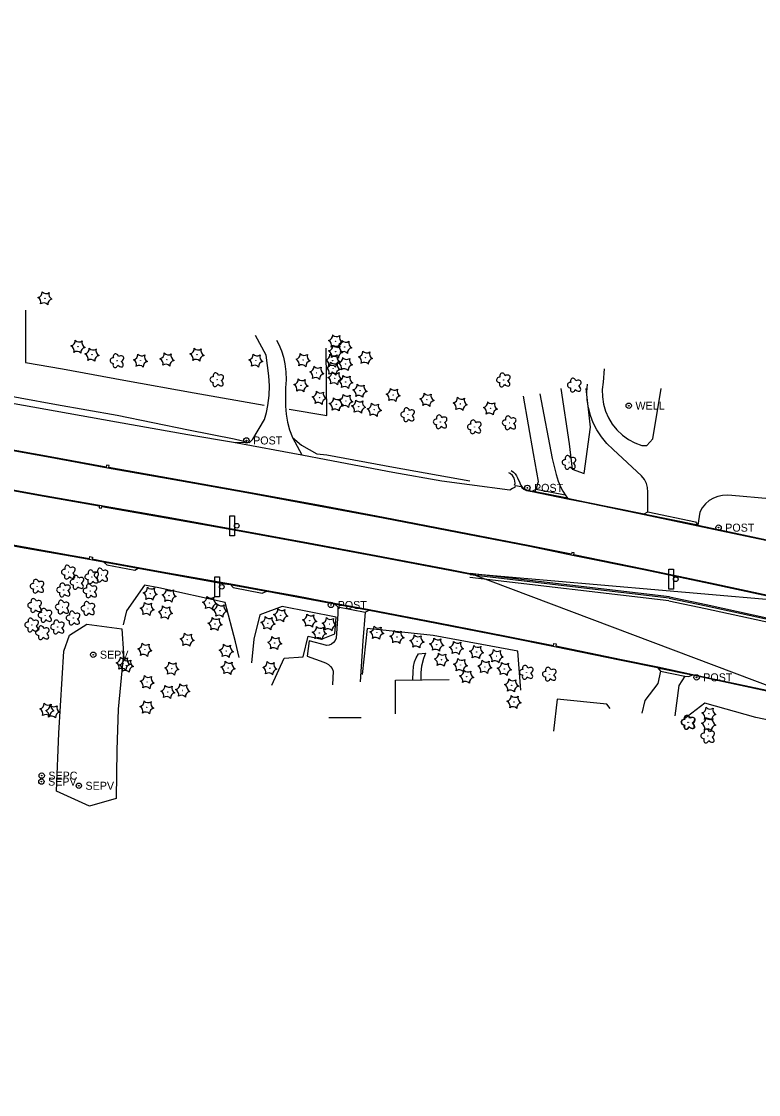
# Model space of a CAD drawing. Extents: x 588843 to 2552415, y 180129 to 269402.
# Drawn here: x 589402 to 589955, y 186560 to 187364 of the extents above; entities that cross this region are included whole.
import ezdxf

# ---------------------------------------------------------------- set-up
doc = ezdxf.new("R2010")
doc.units = 0
for name, color, linetype in [('Default', 7, 'Continuous'), ('E_BLD', 7, 'Continuous'), ('E_FEN_Generic', 7, 'Continuous'), ('E_LAND_TreeLine', 7, 'Continuous'), ('E_LAND_Vegetation', 7, 'Continuous'), ('E_MISCPROP', 7, 'Continuous'), ('E_MISCPROP_Septic', 7, 'Continuous'), ('E_MISCPROP_Well', 7, 'Continuous'), ('E_RDWY', 7, 'Continuous'), ('E_RDWY_AsphConc', 7, 'Continuous'), ('E_RDWY_C_and_G', 7, 'Continuous'), ('E_RDWY_Gravel', 7, 'Continuous'), ('E_SGN', 7, 'Continuous'), ('P_RDWY_C_and_G_30', 7, 'Continuous'), ('P_RDWY_C_and_GFace', 7, 'Continuous'), ('P_RDWY_LaneEdge', 7, 'Continuous')]:
    doc.layers.add(name, color=color, linetype=linetype)

# ---------------------------------------------------------------- blocks, each defined once
blk = doc.blocks.new('CTRE_2')
at = {"layer": 'E_LAND_Vegetation'}
blk.add_circle((0, 0), 0.223, dxfattribs=at)
for centre, start, end in [((-12, 9), 280.2067, 5.9716), ((-13.8, -5.9), 340.2113, 65.9762), ((1.8, 14.9), 220.2113, 305.9762), ((13.8, 5.9), 160.2113, 245.9762), ((-1.8, -14.9), 40.2113, 125.9762), ((12, -9), 100.2511, 185.9272)]:
    blk.add_arc(centre, 7.87, start, end, dxfattribs=at)
blk = doc.blocks.new('DTRE_2')
at = {"layer": 'E_LAND_Vegetation'}
blk.add_circle((-0.2, 0), 0.183, dxfattribs=at)
for centre, major_axis, ratio in [((-5.9, 0.2), (4.93, -0.12), 0.832022), ((-1.9, 5.3), (1.36, -4.98), 0.782863), ((4.1, 2.7), (-5.27, -2.93), 0.691916), ((-2.5, -5.2), (1.8, 4.86), 0.716896), ((3.5, -3.7), (-5.01, 4.58), 0.560249)]:
    blk.add_ellipse(centre, major_axis=major_axis, ratio=ratio, start_param=1.570796, end_param=4.712389, dxfattribs=at)
blk = doc.blocks.new('POST')
at = {"layer": 'E_MISCPROP'}
for radius in [4, 0.5]:
    blk.add_circle((0, 0), radius, dxfattribs=at)
blk.add_text('POST', height=12, dxfattribs=at).set_placement((10, -6))
blk = doc.blocks.new('SEPC')
at = {"layer": 'E_MISCPROP_Septic'}
for radius in [4, 0.5]:
    blk.add_circle((0, 0), radius, dxfattribs=at)
blk.add_text('SEPC', height=12, dxfattribs=at).set_placement((10, -6))
blk = doc.blocks.new('SEPV')
at = {"layer": 'E_MISCPROP_Septic'}
for radius in [4, 0.5]:
    blk.add_circle((0, 0), radius, dxfattribs=at)
blk.add_text('SEPV', height=12, dxfattribs=at).set_placement((10, -6))
blk = doc.blocks.new('SGN')
at = {"layer": 'E_SGN'}
blk.add_lwpolyline([(-3.5, -15), (-10.5, -15), (-10.5, 15), (-3.5, 15)], close=True, dxfattribs=at)
blk.add_circle((0, 0), 3.5, dxfattribs=at)
blk = doc.blocks.new('WELL')
at = {"layer": 'E_MISCPROP_Well'}
for radius in [4, 0.5]:
    blk.add_circle((0, 0), radius, dxfattribs=at)
blk.add_text('WELL', height=12, dxfattribs=at).set_placement((10, -6))

msp = doc.modelspace()

# ---------------------------------------------------------------- linework, layer by layer
at = {"layer": 'Default'}
msp.add_lwpolyline([(591615.09, 187246.23), (591637.48, 187198.53), (591342.5, 186657.05), (591340.04, 186646.33), (591325.15, 186588.94), (591314.68, 186544.52), (590335.16, 185755.94), (590089.6, 186237.3), (590063.71, 186267.8), (589984.27, 186602.34), (590048.74, 186666.43), (590044.21, 186706.17), (589965.01, 186852.44), (589966.96, 186864.3), (589738.46, 186950.56), (589980.48, 186929.54), (589980.82, 186932.54), (589987.79, 186967.01), (589988.43, 186969.95), (590832.85, 187364.29), (591607.16, 187360.88), (591615.35, 187246.35)], dxfattribs=at)
at = {"layer": 'E_BLD'}
for points in [[(589682.51, 186845.31), (589682.41, 186870.77), (589722.57, 186871.09)], [(589843.35, 186849.49), (589840.77, 186852.62), (589803.54, 186856.43), (589800.87, 186832.43)], [(589632.35, 186842.74), (589656.72, 186842.67)]]:
    msp.add_lwpolyline(points, dxfattribs=at)
at = {"layer": 'E_FEN_Generic'}
for points in [[(589405.08, 187147.87), (589405.03, 187108.65), (589432.7, 187103.92), (589478.73, 187095.47), (589531.54, 187085.92), (589583.95, 187076.68)], [(589631.02, 187069.05), (589630.46, 187119.36)], [(589602.77, 187073.62), (589631.02, 187069.05)]]:
    msp.add_lwpolyline(points, dxfattribs=at)
at = {"layer": 'E_LAND_TreeLine'}
for points in [[(589806.4, 187089.18), (589812.59, 187047.85), (589814.83, 187028.66), (589823.77, 187025.6), (589828.69, 187060.14), (589825.39, 187089.23)], [(589565.11, 186887.69), (589562.51, 186899.32), (589554.64, 186928.98), (589504.96, 186939.84), (589494.38, 186941.78), (589480.9, 186922.67), (589478.19, 186912.07)], [(589589.61, 186866.88), (589598.87, 186887.08), (589613.12, 186888.16), (589616.87, 186903.71), (589626.95, 186901.3), (589636.9, 186905.36), (589637.83, 186917.74), (589597.41, 186925.8), (589580.62, 186919.52), (589576.19, 186901.45), (589574.43, 186883.69)], [(589776.39, 186863.13), (589774.02, 186892.48), (589710.6, 186904.03), (589661.22, 186909.42), (589657.46, 186874.81)], [(590014.98, 186732.45), (590063.58, 186738.57), (590112.84, 186742.66), (590160.88, 186749.13), (590170.83, 186760.5), (590178.14, 186789.72), (590132.33, 186804.85), (590080.03, 186813.95), (590043.49, 186822.21), (589999.48, 186833.03), (589952.51, 186842.61), (589914.19, 186853.29), (589898.07, 186840.93)]]:
    msp.add_lwpolyline(points, dxfattribs=at)
at = {"layer": 'E_MISCPROP_Septic'}
msp.add_lwpolyline([(589433.87, 186892.43), (589437.99, 186904.25), (589451.03, 186912.69), (589477.28, 186909.03), (589478.46, 186890.74), (589474.46, 186848.94), (589473.62, 186818.31), (589473.15, 186781.94), (589453.13, 186776.31), (589428.41, 186787.56), (589430.04, 186830.87)], close=True, dxfattribs=at)
at = {"layer": 'E_RDWY'}
for points in [[(589561.02, 187048.9), (589573.02, 187048.74), (589575.56, 187051.35), (589584.2, 187066.08), (589585.61, 187071.3), (589586.7, 187076.6), (589586.7, 187076.6), (589587.62, 187083.94), (589587.9, 187091.33), (589587.54, 187098.72), (589587.54, 187098.72), (589585.46, 187114.21), (589577.41, 187128.97)], [(589593.28, 187125.56), (589595.04, 187122.11), (589596.89, 187117.44), (589598.36, 187112.63), (589599.43, 187107.73), (589599.43, 187107.73), (589600.19, 187101.72), (589600.35, 187095.68), (589599.92, 187089.64), (589599.92, 187089.64), (589599.9, 187075.88), (589600.36, 187069.89), (589601.39, 187063.96), (589602.98, 187058.16), (589602.98, 187058.16), (589605.16, 187052.42), (589605.16, 187052.42), (589612.18, 187039.61)], [(589838.72, 187103.98), (589838.05, 187094.08), (589837.42, 187088.59), (589837.51, 187083.07), (589838.34, 187077.6), (589839.87, 187072.3), (589842.09, 187067.24), (589844.96, 187062.52), (589844.96, 187062.52), (589844.96, 187062.52), (589848.44, 187058.19), (589852.47, 187054.37), (589856.97, 187051.11), (589861.86, 187048.48), (589867.06, 187046.52), (589867.06, 187046.52), (589870.94, 187046.41), (589875.24, 187051.53), (589881.49, 187089.14)], [(589871.7, 186996.71), (589871.68, 187011.63), (589871.42, 187014.92), (589870.54, 187018.09), (589870.54, 187018.09), (589869, 187021.14), (589866.9, 187023.82), (589866.9, 187023.82), (589845.56, 187043.63), (589840.92, 187048.01), (589836.82, 187052.89), (589833.32, 187058.22), (589833.32, 187058.22), (589830.63, 187063.5), (589828.54, 187069.05), (589827.05, 187074.78), (589826.19, 187080.65), (589825.97, 187086.57), (589826.4, 187092.48), (589826.4, 187092.48), (589826.4, 187092.48)], [(589787.9, 187013.85), (589789.53, 187019.46), (589785.99, 187040.49), (589778.28, 187083.47)], [(589790.51, 187085.17), (589799.93, 187036.88), (589802.89, 187024.83), (589804.34, 187019.84), (589806.35, 187015.04), (589806.35, 187015.04), (589807.82, 187012.27), (589809.49, 187009.61), (589809.49, 187009.61)], [(589965.6, 187090.54), (589965.17, 187054), (589962.88, 187006.44), (589934.47, 187009.04), (589931, 187009.36), (589927.53, 187009.14), (589924.13, 187008.39), (589920.89, 187007.11), (589920.89, 187007.11), (589917.66, 187005.2), (589914.81, 187002.77), (589912.39, 186999.9), (589910.49, 186996.67), (589910.49, 186996.67), (589909.16, 186986.87)], [(589372.62, 187082.17), (589427.26, 187072.37), (589473.22, 187064.16), (589526.69, 187054.74), (589561.02, 187048.9), (589612.18, 187039.61), (589630.34, 187036.06), (589680.41, 187026.44), (589717.23, 187020), (589737.9, 187017.33), (589768.13, 187013.41), (589770.12, 187014.57), (589772.19, 187015.27), (589772.46, 187016.44), (589776.62, 187015.67), (589777.18, 187014.99), (589778.57, 187013.82), (589778.57, 187013.82), (589780.62, 187012.84), (589780.62, 187012.84), (589784.85, 187011.92), (589811.4, 187006.57), (589824.26, 187003.96), (589868.73, 186994.69), (589908.97, 186986.39), (589925.47, 186982.93), (589984.99, 186970.24)], [(589977.73, 186930.63), (589918.47, 186943.34), (589868.51, 186953.89), (589816.22, 186964.61), (589816.46, 186966), (589814.61, 186966.4), (589814.24, 186964.98), (589781.92, 186971.46), (589730.12, 186981.57), (589673.33, 186992.61), (589624.74, 187001.68), (589571, 187011.48), (589520.88, 187020.41), (589467.58, 187030), (589467.78, 187031.44), (589465.9, 187031.84), (589465.59, 187030.38), (589420.78, 187038.48), (589366.35, 187048.18)], [(589361.36, 187018.98), (589414.74, 187009.38), (589460.39, 187001.28), (589460.18, 186999.88), (589461.93, 186999.54), (589462.2, 187000.92), (589514.68, 186991.65), (589563.86, 186982.74), (589616.98, 186973.1), (589667.83, 186963.63), (589723.19, 186953.07), (589738.52, 186950.06)], [(589353.39, 186979.53), (589404.18, 186970.46), (589440.06, 186964.03), (589453.05, 186961.82), (589453.3, 186963.27), (589455.17, 186962.91), (589454.92, 186961.51), (589463.6, 186959.94), (589489.65, 186955.16), (589507.48, 186951.83), (589554.46, 186943.52), (589558.88, 186942.72), (589586.08, 186937.82), (589608.52, 186933.73), (589636.67, 186928.48), (589662.7, 186923.58), (589713.4, 186913.84), (589765.71, 186903.54), (589800.74, 186896.64), (589801.13, 186898.12), (589802.88, 186897.85), (589802.68, 186896.37), (589851.85, 186886.15), (589879.01, 186880.52), (589905.38, 186874.97), (589960.82, 186863.13)], [(589639.17, 186925.49), (589639.14, 186920.29), (589637.85, 186902.24), (589637.19, 186900.41), (589636.05, 186898.83), (589634.51, 186897.63), (589634.51, 186897.63), (589632.77, 186896.93), (589630.91, 186896.72), (589630.91, 186896.72), (589617.64, 186900.13), (589616.22, 186888.67), (589628.58, 186884.26), (589630.49, 186883.51), (589632.22, 186882.42), (589633.71, 186881.01), (589633.71, 186881.01), (589634.9, 186879.36), (589635.76, 186877.52), (589635.76, 186877.52), (589635.16, 186867.24)], [(589659.78, 186921.54), (589657.91, 186900.04), (589655.97, 186869.37)], [(589880.98, 186877.5), (589879.11, 186868.07), (589869.22, 186855.51), (589867.2, 186845.86)], [(589899.3, 186873.57), (589894.76, 186866.74), (589891.92, 186843.99)]]:
    msp.add_lwpolyline(points, dxfattribs=at)
at = {"layer": 'E_RDWY_AsphConc'}
for points in [[(589784.99, 187012.34), (589787.9, 187013.85), (589809.49, 187009.61), (589811.38, 187007.1)], [(589868.9, 186995.31), (589871.7, 186996.71), (589907.23, 186989.23), (589909.16, 186986.87)], [(589463.47, 186959.44), (589466.05, 186957.19), (589486.94, 186953.09), (589489.53, 186954.56)], [(589558.81, 186942.23), (589560.81, 186940.11), (589582.49, 186935.87), (589585.95, 186937.31)], [(589636.7, 186927.94), (589639.17, 186925.49), (589659.78, 186921.54), (589662.7, 186923)], [(589695.37, 186871.04), (589695.65, 186877.02), (589695.81, 186880.78), (589696.63, 186884.45), (589696.63, 186884.45), (589697.86, 186887.51), (589699.54, 186890.34), (589699.54, 186890.34), (589704.87, 186890.78), (589703.32, 186886.97), (589701.95, 186881.16), (589701.95, 186881.16), (589701.37, 186876.46), (589701.37, 186876.46), (589701.34, 186870.96)], [(589878.86, 186880.04), (589880.98, 186877.5), (589899.3, 186873.57), (589902.34, 186873.3), (589905.08, 186874.55)]]:
    msp.add_lwpolyline(points, dxfattribs=at)
at = {"layer": 'E_RDWY_C_and_G'}
for points in [[(589977.55, 186930.13), (589918.31, 186942.9), (589868.47, 186953.29), (589815.16, 186964.2), (589781.77, 186970.99), (589730, 186981.13), (589673.25, 186992.17), (589624.58, 187001.14), (589570.94, 187010.92), (589520.62, 187019.99), (589466.47, 187029.65), (589420.83, 187037.9), (589366.16, 187047.65)], [(589769.16, 187027.9), (589770.91, 187026.41), (589772.17, 187025.18), (589773.21, 187023.75), (589773.21, 187023.75), (589773.96, 187022.27), (589773.96, 187022.27), (589775.67, 187018.49), (589776.24, 187017.11), (589777.06, 187015.86), (589777.06, 187015.86), (589778.69, 187014.34), (589780.69, 187013.34), (589780.69, 187013.34), (589784.99, 187012.34), (589785.9, 187012.23), (589810.02, 187007.42), (589811.38, 187007.1), (589824.39, 187004.41), (589868.9, 186995.31), (589869.66, 186995.11), (589907.92, 186987.23), (589909.16, 186986.87), (589925.72, 186983.38), (589985.18, 186970.66)], [(589361.45, 187019.53), (589414.83, 187009.91), (589514.78, 186992.2), (589564.07, 186983.31), (589617.16, 186973.61), (589667.99, 186964.17), (589723.28, 186953.52), (589738.46, 186950.56)], [(589771.7, 187016.68), (589772.13, 187018.1), (589771.97, 187020.15), (589771.33, 187022.09), (589771.33, 187022.09), (589770.09, 187024.02), (589768.37, 187025.55), (589768.37, 187025.55), (589767.46, 187026.14)], [(589353.38, 186979.03), (589404.09, 186969.91), (589439.93, 186963.61), (589453.98, 186961.18), (589463.47, 186959.44), (589464.71, 186959.2), (589488.38, 186954.83), (589489.53, 186954.56), (589507.31, 186951.3), (589554.36, 186942.91), (589558.81, 186942.23), (589559.78, 186942.05), (589584.27, 186937.51), (589585.95, 186937.31), (589608.44, 186933.16), (589636.7, 186927.94), (589637.87, 186927.67), (589661.38, 186923.24), (589662.7, 186923), (589713.22, 186913.32), (589765.61, 186903.02), (589801.55, 186895.91), (589851.67, 186885.69), (589878.86, 186880.04), (589880.03, 186879.72), (589903.63, 186874.82), (589905.08, 186874.55), (589960.75, 186862.61)]]:
    msp.add_lwpolyline(points, dxfattribs=at)
at = {"layer": 'E_RDWY_Gravel'}
for points in [[(589014.46, 187248.67), (589012.5, 187215.74), (589012.78, 187204.67), (589013.84, 187193.64), (589013.84, 187193.64), (589015.34, 187184.4), (589017.4, 187175.26), (589017.4, 187175.26), (589025.04, 187159.45), (589039.39, 187149.24), (589063.58, 187143.87), (589113.01, 187134.42), (589164.63, 187124.63), (589219.01, 187114.58), (589273.12, 187104.99), (589323.17, 187096.7), (589373.47, 187087.16), (589428.23, 187077.23), (589473.87, 187069.16), (589527.37, 187058.14), (589561.37, 187051.4), (589573.02, 187048.74)], [(589605.16, 187052.42), (589611.88, 187046.72), (589623.53, 187040.18), (589631.05, 187039.47), (589680.88, 187030.35), (589738.1, 187019.91)]]:
    msp.add_lwpolyline(points, dxfattribs=at)
at = {"layer": 'P_RDWY_C_and_G_30'}
for points in [[(589887.78, 186933.01), (589738.46, 186950.56)], [(589887.78, 186933.01), (589738.46, 186950.56)], [(589887.78, 186933.01), (589915.39, 186927.24), (589985.72, 186911.99)]]:
    msp.add_lwpolyline(points, dxfattribs=at)
at = {"layer": 'P_RDWY_C_and_GFace'}
for points in [[(589887.62, 186932.02), (589738.34, 186949.57)], [(589887.62, 186932.02), (589738.34, 186949.57)], [(589887.62, 186932.02), (589915.18, 186926.26), (589985.51, 186911.01)]]:
    msp.add_lwpolyline(points, dxfattribs=at)
at = {"layer": 'P_RDWY_LaneEdge'}
for points in [[(589887.3, 186930.04), (589738.11, 186947.58)], [(589887.3, 186930.04), (589738.11, 186947.58)], [(589887.3, 186930.04), (589914.76, 186924.31), (589985.08, 186909.06)]]:
    msp.add_lwpolyline(points, dxfattribs=at)

# ---------------------------------------------------------------- block references
at = {"layer": 'E_LAND_Vegetation', "xscale": 0.5, "yscale": 0.5}
for name, p in [('CTRE_2', (589419.63, 187156.86)), ('CTRE_2', (589444.41, 187120.57)), ('CTRE_2', (589637.42, 187124.56)), ('CTRE_2', (589644.35, 187120.4)), ('CTRE_2', (589454.94, 187114.56)), ('CTRE_2', (589511.11, 187110.94)), ('CTRE_2', (589533.62, 187114.6)), ('CTRE_2', (589637.56, 187116.78)), ('CTRE_2', (589659.97, 187112.36)), ('DTRE_2', (589473.83, 187110.01)), ('CTRE_2', (589491.27, 187110.12)), ('CTRE_2', (589577.73, 187110.14)), ('CTRE_2', (589613.16, 187110.49)), ('CTRE_2', (589635.4, 187110.08)), ('CTRE_2', (589635.71, 187104.17)), ('CTRE_2', (589644.91, 187107.53)), ('DTRE_2', (589548.74, 187095.76)), ('CTRE_2', (589623.42, 187100.98)), ('CTRE_2', (589636.92, 187096.92)), ('DTRE_2', (589763.58, 187095.61)), ('CTRE_2', (589611.55, 187091.59)), ('CTRE_2', (589645.12, 187094.15)), ('CTRE_2', (589655.82, 187087.56)), ('DTRE_2', (589816.69, 187091.71)), ('CTRE_2', (589625.33, 187082.25)), ('CTRE_2', (589645.19, 187079.93)), ('CTRE_2', (589680.64, 187084.4)), ('CTRE_2', (589706.01, 187080.76)), ('CTRE_2', (589638.06, 187077.33)), ('CTRE_2', (589654.75, 187075.68)), ('CTRE_2', (589666.51, 187073.27)), ('CTRE_2', (589730.92, 187077.72)), ('CTRE_2', (589753.61, 187074.32)), ('DTRE_2', (589691.79, 187069.56)), ('DTRE_2', (589716.16, 187064.18)), ('DTRE_2', (589767.9, 187063.47)), ('DTRE_2', (589741.71, 187060.43)), ('DTRE_2', (589812.66, 187033.8)), ('DTRE_2', (589437.49, 186951.57)), ('DTRE_2', (589462, 186949.35)), ('DTRE_2', (589443.91, 186943.95)), ('DTRE_2', (589454.99, 186948.03)), ('DTRE_2', (589413.94, 186941.02)), ('DTRE_2', (589433.83, 186938.23)), ('DTRE_2', (589453.71, 186937.55)), ('CTRE_2', (589498.54, 186935.46)), ('CTRE_2', (589512.71, 186933.96)), ('DTRE_2', (589412.19, 186926.58)), ('DTRE_2', (589432.79, 186925.36)), ('CTRE_2', (589543.11, 186928.56)), ('DTRE_2', (589419.94, 186919.25)), ('DTRE_2', (589440.99, 186917.19)), ('DTRE_2', (589452.08, 186924.36)), ('CTRE_2', (589496.27, 186924.05)), ('CTRE_2', (589509.95, 186921.34)), ('CTRE_2', (589550.85, 186922.79)), ('CTRE_2', (589596.33, 186919.3)), ('DTRE_2', (589409.96, 186911.93)), ('DTRE_2', (589429.28, 186910.46)), ('CTRE_2', (589547.17, 186912.7)), ('CTRE_2', (589586.82, 186913.35)), ('CTRE_2', (589618.07, 186915.28)), ('CTRE_2', (589632.73, 186912.63)), ('DTRE_2', (589417.93, 186906.15)), ('CTRE_2', (589625.37, 186906.02)), ('CTRE_2', (589668.42, 186906.2)), ('CTRE_2', (589683.51, 186903.02)), ('CTRE_2', (589526.29, 186900.94)), ('CTRE_2', (589591.91, 186898.44)), ('CTRE_2', (589698.56, 186899.67)), ('CTRE_2', (589713.27, 186897.3)), ('CTRE_2', (589728.08, 186894.81)), ('CTRE_2', (589494.51, 186893.4)), ('CTRE_2', (589555.59, 186892.61)), ('CTRE_2', (589716.86, 186885.93)), ('CTRE_2', (589743.19, 186891.73)), ('CTRE_2', (589757.91, 186888.65)), ('CTRE_2', (589478.25, 186883.06)), ('CTRE_2', (589480.72, 186881.48)), ('CTRE_2', (589514.71, 186879.35)), ('CTRE_2', (589556.87, 186879.88)), ('CTRE_2', (589588.25, 186879.61)), ('CTRE_2', (589731.14, 186881.98)), ('CTRE_2', (589749.39, 186880.62)), ('CTRE_2', (589764.01, 186879.09)), ('CTRE_2', (589735.8, 186873.23)), ('DTRE_2', (589780.7, 186876.5)), ('DTRE_2', (589797.96, 186875.1)), ('CTRE_2', (589496.27, 186869.17)), ('CTRE_2', (589511.72, 186861.86)), ('CTRE_2', (589522.91, 186862.91)), ('CTRE_2', (589769.51, 186866.73)), ('CTRE_2', (589771.24, 186854.27)), ('CTRE_2', (589421.11, 186848.42)), ('CTRE_2', (589425.5, 186847.24)), ('CTRE_2', (589496, 186850.27)), ('CTRE_2', (589917.35, 186845.46)), ('DTRE_2', (589901.84, 186839.08)), ('DTRE_2', (589902.19, 186838.99)), ('CTRE_2', (589917.16, 186837.68)), ('DTRE_2', (589916.74, 186828.72))]:
    msp.add_blockref(name, p, dxfattribs=at)
at = {"layer": 'E_MISCPROP', "xscale": 0.5, "yscale": 0.5}
for p in [(589570.68, 187050.3), (589781.25, 187014.75), (589924.6, 186984.96), (589634.06, 186927), (589908.1, 186872.76)]:
    msp.add_blockref('POST', p, dxfattribs=at)
at = {"layer": 'E_MISCPROP_Septic', "xscale": 0.5, "yscale": 0.5}
for name, p in [('SEPV', (589455.85, 186889.74)), ('SEPC', (589417.2, 186799.11)), ('SEPV', (589416.97, 186794.62)), ('SEPV', (589445.03, 186791.52))]:
    msp.add_blockref(name, p, dxfattribs=at)
at = {"layer": 'E_MISCPROP_Well', "xscale": 0.5, "yscale": 0.5}
msp.add_blockref('WELL', (589857.29, 187076.34), dxfattribs=at)
at = {"layer": 'E_SGN', "xscale": 0.5, "yscale": 0.5}
for p in [(589563.43, 186986.4), (589552.21, 186940.6), (589892.5, 186946.31)]:
    msp.add_blockref('SGN', p, dxfattribs=at)

doc.saveas('drawing.dxf')
